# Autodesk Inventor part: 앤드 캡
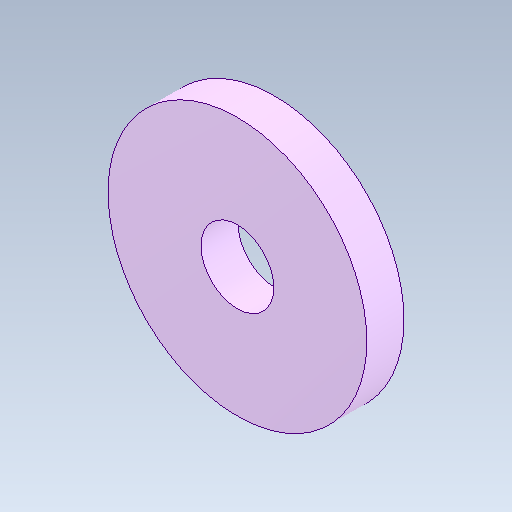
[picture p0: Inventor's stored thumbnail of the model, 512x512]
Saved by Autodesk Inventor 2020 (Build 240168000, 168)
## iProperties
Created: 2024-04
Part Number: 앤드 캡
Material: 강철, 연강
Document SubType Name: Modeling
Designer: oem
Density: 7.86 g/cm^3
Appearance: 기본값
Mass: 3.34728 g
Surface Area: 5.18441 cm^2
Volume: 0.425863 cm^3
Sending System: Autodesk Inventor 2025
Preprocessor: ST-DEVELOPER v20
Author: jhkim
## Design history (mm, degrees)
feature "솔리드1"
node "솔리드2"
